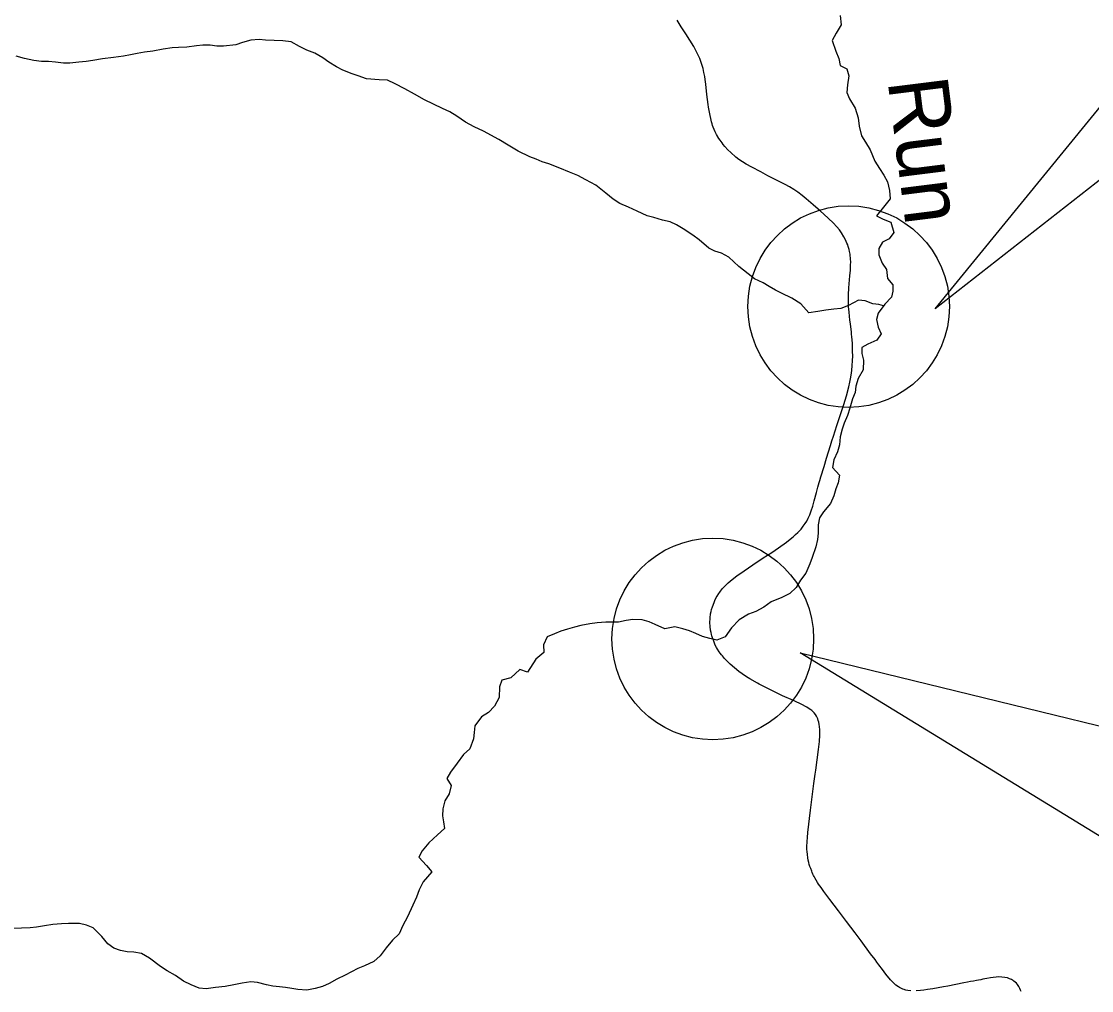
# Model space of a CAD drawing. Extents: x -12.1 to 34, y 0 to 22.
# Drawn here: x 3.691 to 5.273, y 14.772 to 16.204 of the extents above; entities that cross this region are included whole.
import ezdxf

# ---------------------------------------------------------------- set-up
doc = ezdxf.new("R2010")
doc.units = 0
for name, color, linetype in [('BR_P_Gen_Text', 7, 'Continuous'), ('Default', 7, 'Continuous'), ('GM_X_Minor_River', 7, 'Continuous'), ('GM_X_Minor_River_Text', 7, 'Continuous'), ('GM_X_State_Route', 7, 'Continuous')]:
    doc.layers.add(name, color=color, linetype=linetype)

msp = doc.modelspace()

# ---------------------------------------------------------------- linework, layer by layer
at = {"layer": 'BR_P_Gen_Text'}
for points in [[(5.7213, 16.6121), (5.7213, 16.3119), (5.0417, 15.7796)], [(5.6572, 15.0721), (5.6572, 14.7719), (4.8418, 15.271)]]:
    msp.add_lwpolyline(points, close=True, dxfattribs=at)
at = {"layer": 'Default'}
for centre in [(4.9136, 15.7828), (4.7128, 15.2916)]:
    msp.add_circle(centre, 0.149, dxfattribs=at)
at = {"layer": 'GM_X_Minor_River'}
for points in [[(4.9012, 16.2129), (4.9024, 16.1994), (4.8951, 16.1869), (4.8895, 16.1762), (4.8946, 16.1606), (4.899, 16.1496), (4.9012, 16.1394), (4.9108, 16.1345), (4.9138, 16.1238), (4.9118, 16.1107), (4.9108, 16.0993), (4.9148, 16.0898), (4.9234, 16.0763), (4.9278, 16.0618), (4.9293, 16.0494), (4.9327, 16.0352), (4.9384, 16.0257), (4.9453, 16.0147), (4.9525, 15.9977), (4.9594, 15.9868), (4.9658, 15.9773), (4.9709, 15.967), (4.9739, 15.9546), (4.975, 15.9422), (4.9652, 15.93), (4.955, 15.9171), (4.9647, 15.9122), (4.9761, 15.9074), (4.9805, 15.8925), (4.9735, 15.8832), (4.9639, 15.8781), (4.9583, 15.8685), (4.9581, 15.8592), (4.9631, 15.8468), (4.9696, 15.8377), (4.9712, 15.8245), (4.9787, 15.815), (4.9788, 15.8058), (4.9771, 15.7969), (4.9672, 15.7865), (4.9574, 15.7729), (4.9547, 15.7636), (4.9573, 15.7526), (4.9616, 15.7424), (4.9553, 15.7331), (4.9422, 15.7273), (4.9331, 15.7226), (4.9331, 15.7137), (4.9354, 15.7037), (4.9351, 15.6895), (4.9278, 15.6767), (4.9244, 15.6653), (4.9234, 15.6557), (4.9192, 15.6464), (4.9154, 15.6325), (4.912, 15.6218)], [(4.9653, 15.7838), (4.9584, 15.7857), (4.9495, 15.7867), (4.9381, 15.7912), (4.9282, 15.7925), (4.9133, 15.7845), (4.902, 15.7802), (4.8917, 15.779), (4.8801, 15.7775), (4.868, 15.7756), (4.8549, 15.7737), (4.8431, 15.7871), (4.8295, 15.7954), (4.8142, 15.8028), (4.8053, 15.8073), (4.7963, 15.8125), (4.7874, 15.8181), (4.7746, 15.8237), (4.7653, 15.8314), (4.7514, 15.8423), (4.7367, 15.856), (4.7256, 15.8616), (4.716, 15.865), (4.7071, 15.8692), (4.6925, 15.8815), (4.6835, 15.8882), (4.6689, 15.898), (4.6593, 15.9039), (4.6496, 15.9081), (4.6386, 15.9108), (4.6255, 15.9143), (4.6159, 15.917), (4.6009, 15.924), (4.5884, 15.9299), (4.5756, 15.9354), (4.5656, 15.9417), (4.5549, 15.9505), (4.5399, 15.9621), (4.5252, 15.9701), (4.5135, 15.9764), (4.501, 15.9816), (4.4868, 15.9875), (4.4704, 15.9938), (4.4604, 15.9969), (4.4515, 16.0007), (4.4423, 16.0041), (4.4252, 16.0125), (4.4102, 16.0212), (4.3966, 16.0296), (4.3738, 16.0422), (4.3599, 16.0485), (4.3471, 16.0554), (4.3346, 16.0642), (4.3242, 16.0705), (4.3132, 16.0757), (4.3, 16.082), (4.2864, 16.0882), (4.2718, 16.0966), (4.2576, 16.1047), (4.2433, 16.112), (4.2319, 16.1176), (4.2195, 16.1178), (4.201, 16.1197), (4.1885, 16.1239), (4.1796, 16.127), (4.1661, 16.1325), (4.1565, 16.1371), (4.1454, 16.1441), (4.1365, 16.1504), (4.1244, 16.1574), (4.1126, 16.1619), (4.1019, 16.1671), (4.0895, 16.1741), (4.077, 16.1757), (4.0646, 16.1763), (4.0515, 16.1765), (4.0422, 16.1775), (4.0298, 16.1767), (4.0174, 16.173), (4.0075, 16.1697), (3.9895, 16.1678), (3.9795, 16.168), (3.9699, 16.169), (3.9589, 16.1692), (3.9494, 16.1681), (3.9352, 16.1662), (3.9231, 16.166), (3.9136, 16.1652), (3.9001, 16.1633), (3.8849, 16.1603), (3.8728, 16.1588), (3.8618, 16.1569), (3.8519, 16.155), (3.8416, 16.1528), (3.8271, 16.1509), (3.8105, 16.1489), (3.7963, 16.1467), (3.7864, 16.1451), (3.7757, 16.144), (3.7626, 16.1428), (3.753, 16.1427)], [(3.753, 16.1427), (3.7413, 16.1443), (3.731, 16.1449), (3.7204, 16.1452), (3.709, 16.1465), (3.6955, 16.1496), (3.6831, 16.153)], [(4.912, 15.6218), (4.9068, 15.6107), (4.904, 15.6015), (4.9013, 15.5901), (4.9003, 15.5783), (4.8972, 15.568), (4.8917, 15.5562), (4.8896, 15.5448), (4.9, 15.5336), (4.898, 15.5222), (4.8945, 15.5133), (4.8918, 15.5029), (4.8866, 15.4919), (4.8764, 15.4797), (4.8705, 15.4704), (4.8684, 15.4601), (4.8685, 15.448), (4.8676, 15.4387), (4.8652, 15.4277), (4.8596, 15.412), (4.8562, 15.4027), (4.8503, 15.3888), (4.8426, 15.3785), (4.8359, 15.3677), (4.8268, 15.3588), (4.8148, 15.353), (4.7992, 15.3464), (4.7883, 15.3388), (4.7766, 15.332), (4.7657, 15.328), (4.7519, 15.32), (4.7403, 15.3078), (4.7309, 15.2949), (4.7188, 15.2898), (4.7082, 15.2922), (4.6975, 15.2953), (4.6875, 15.2995), (4.6783, 15.3037), (4.6687, 15.3068), (4.6569, 15.3095), (4.6421, 15.3065), (4.6274, 15.3131), (4.6185, 15.3169), (4.6086, 15.32), (4.5947, 15.3206), (4.5848, 15.3191), (4.5735, 15.3165), (4.5547, 15.3163), (4.5419, 15.3155), (4.5309, 15.3139), (4.5178, 15.3113), (4.5086, 15.3091), (4.498, 15.3062), (4.4881, 15.3029), (4.4786, 15.2992), (4.468, 15.2945), (4.4627, 15.2831), (4.4629, 15.2714), (4.4512, 15.2616), (4.439, 15.2423), (4.4276, 15.2465), (4.4142, 15.2339), (4.4011, 15.2306), (4.3973, 15.221), (4.3968, 15.205), (4.3901, 15.1921), (4.3813, 15.1831), (4.3711, 15.1767), (4.361, 15.1634), (4.36, 15.1535), (4.359, 15.1442), (4.3538, 15.1292), (4.3443, 15.121), (4.3349, 15.1081), (4.325, 15.0948), (4.3198, 15.0855), (4.3263, 15.0749), (4.3232, 15.0625), (4.3166, 15.0525), (4.3135, 15.0404), (4.3132, 15.0304), (4.3147, 15.0212), (4.3162, 15.0112), (4.306, 15.0023), (4.293, 14.9904), (4.2832, 14.9782), (4.2783, 14.9689), (4.2898, 14.9566), (4.2973, 14.9475), (4.2847, 14.9328), (4.2788, 14.9206), (4.2746, 14.9099), (4.2694, 14.8982), (4.2614, 14.881), (4.2548, 14.8682), (4.2492, 14.8557), (4.2393, 14.8463), (4.2299, 14.8349), (4.2211, 14.8234), (4.2116, 14.8148), (4.1978, 14.8086)], [(4.1978, 14.8086), (4.1883, 14.8046), (4.1692, 14.7948), (4.1569, 14.7887), (4.1459, 14.7825), (4.136, 14.7778), (4.1251, 14.7748), (4.1127, 14.7726), (4.0995, 14.7735), (4.0903, 14.7749), (4.0814, 14.7762), (4.0725, 14.7775), (4.0626, 14.7785), (4.0533, 14.7805), (4.0398, 14.784), (4.0299, 14.7846), (4.0171, 14.7827), (4.0047, 14.7804), (3.992, 14.7778), (3.9778, 14.7762), (3.964, 14.7747), (3.9537, 14.7753), (3.9416, 14.7805), (3.9302, 14.7857), (3.9184, 14.7941), (3.9063, 14.8011), (3.8963, 14.8074), (3.8802, 14.82), (3.8681, 14.8267), (3.8571, 14.8287), (3.8471, 14.8293), (3.8375, 14.8313), (3.8272, 14.8348), (3.8183, 14.8411), (3.8097, 14.8517), (3.7968, 14.8647), (3.7871, 14.8685), (3.7765, 14.8709), (3.7602, 14.8711), (3.7499, 14.8703), (3.7371, 14.8694), (3.7247, 14.8675), (3.713, 14.8656), (3.7038, 14.8648), (3.691, 14.8643), (3.6761, 14.8635)]]:
    msp.add_lwpolyline(points, dxfattribs=at)
at = {"layer": 'GM_X_State_Route'}
for points in [[(4.7093, 15.3269), (4.7096, 15.3289), (4.7102, 15.3322), (4.7109, 15.3349), (4.7123, 15.3393), (4.7147, 15.3456), (4.7158, 15.3483), (4.718, 15.3528), (4.7192, 15.3549), (4.7217, 15.3587), (4.723, 15.3606), (4.7268, 15.3655), (4.7301, 15.3691), (4.7316, 15.3707), (4.7354, 15.3744), (4.7413, 15.3796), (4.7483, 15.385), (4.759, 15.3923), (4.772, 15.401), (4.7874, 15.4113), (4.8, 15.4196), (4.8101, 15.4265), (4.8219, 15.4349), (4.8274, 15.4392), (4.8314, 15.4425), (4.8353, 15.4459), (4.8386, 15.449), (4.8407, 15.4511), (4.8434, 15.4541), (4.8466, 15.4581), (4.8494, 15.462), (4.8516, 15.4657), (4.8539, 15.47), (4.8561, 15.4751), (4.8582, 15.4808), (4.8605, 15.488), (4.8627, 15.4957), (4.866, 15.508), (4.8682, 15.5159), (4.8701, 15.5229), (4.871, 15.526), (4.8725, 15.5312), (4.8772, 15.5464), (4.881, 15.5588), (4.8838, 15.568), (4.8867, 15.5775), (4.8889, 15.5845), (4.8911, 15.5914), (4.8963, 15.6073), (4.9026, 15.6264), (4.9063, 15.6381), (4.9102, 15.651), (4.9139, 15.6643), (4.9153, 15.671), (4.9164, 15.676), (4.9168, 15.6785), (4.9178, 15.685), (4.9182, 15.6886), (4.919, 15.6958), (4.9194, 15.7027), (4.9196, 15.7103), (4.9195, 15.7166), (4.9195, 15.7221), (4.9192, 15.7281), (4.9188, 15.7339), (4.9184, 15.7383), (4.918, 15.7422), (4.9176, 15.7457), (4.9172, 15.7491), (4.9162, 15.7575), (4.9155, 15.7628), (4.9143, 15.7745), (4.9136, 15.7828), (4.9134, 15.7905), (4.9132, 15.8003), (4.9138, 15.8104), (4.9154, 15.8282), (4.9163, 15.8368), (4.9166, 15.8434), (4.9167, 15.8495), (4.9166, 15.8524), (4.9157, 15.8605), (4.9149, 15.8644), (4.9142, 15.8673), (4.9129, 15.8717), (4.9122, 15.874), (4.9111, 15.8767), (4.9089, 15.8817), (4.9066, 15.8861), (4.903, 15.8918), (4.8999, 15.8961), (4.8962, 15.9006), (4.8907, 15.9064), (4.884, 15.9128), (4.8767, 15.9195), (4.8718, 15.9238), (4.8612, 15.9332), (4.8506, 15.9422), (4.8449, 15.947), (4.8385, 15.9519), (4.8326, 15.9559), (4.8262, 15.9597), (4.82, 15.9631), (4.8082, 15.9692), (4.7944, 15.9763), (4.7837, 15.982), (4.7704, 15.9888), (4.7623, 15.9932), (4.7567, 15.9967), (4.7515, 16.0003), (4.7469, 16.0039), (4.7397, 16.0104), (4.7352, 16.0146), (4.7308, 16.0195), (4.7283, 16.0225), (4.7265, 16.025), (4.7237, 16.0288), (4.7219, 16.0315), (4.7184, 16.0374), (4.7164, 16.0413), (4.715, 16.0444), (4.7134, 16.048), (4.7125, 16.0507), (4.7118, 16.0528), (4.7109, 16.0559), (4.7104, 16.0584), (4.7084, 16.0675), (4.7065, 16.0778), (4.706, 16.0815), (4.7042, 16.0964), (4.7026, 16.1116), (4.7017, 16.1186), (4.701, 16.1228), (4.6997, 16.129), (4.6984, 16.1346), (4.6961, 16.1423), (4.6934, 16.1496), (4.6899, 16.1573), (4.6846, 16.1673), (4.6787, 16.1768), (4.6728, 16.1859), (4.6662, 16.1961), (4.6599, 16.2062)], [(5.0054, 14.7715), (5.001, 14.7721), (4.998, 14.7727), (4.9967, 14.773), (4.9956, 14.7734), (4.9936, 14.7742), (4.9917, 14.775), (4.9888, 14.7766), (4.9874, 14.7774), (4.9836, 14.78), (4.9808, 14.7825), (4.9793, 14.7839), (4.9757, 14.7877), (4.9688, 14.7962), (4.9636, 14.803), (4.9584, 14.8099), (4.9554, 14.8139), (4.9526, 14.8176), (4.9459, 14.8264), (4.9319, 14.8456), (4.9231, 14.857), (4.9103, 14.8742), (4.8984, 14.8898), (4.8859, 14.9063), (4.8771, 14.9181), (4.8728, 14.9242), (4.8691, 14.9294), (4.8676, 14.9318), (4.8636, 14.9387), (4.8626, 14.9404), (4.8617, 14.9422), (4.8609, 14.9438), (4.8599, 14.9462), (4.859, 14.9482), (4.8575, 14.9521), (4.8563, 14.9554), (4.8555, 14.9581), (4.8547, 14.961), (4.8539, 14.9645), (4.8533, 14.9679), (4.8526, 14.973), (4.8521, 14.9775), (4.852, 14.9804), (4.8519, 14.9842), (4.8524, 14.9924), (4.8527, 14.9981), (4.8533, 15.0057), (4.8571, 15.0385), (4.8622, 15.078), (4.8642, 15.0919), (4.865, 15.0976), (4.8669, 15.113), (4.869, 15.1284), (4.8704, 15.1398), (4.8709, 15.1493), (4.871, 15.1519), (4.8708, 15.1571), (4.8704, 15.1621), (4.87, 15.165), (4.8694, 15.1685), (4.8687, 15.1711), (4.8679, 15.1733), (4.867, 15.1754), (4.866, 15.1776), (4.8646, 15.1798), (4.8625, 15.1825), (4.8604, 15.1847), (4.859, 15.186), (4.8577, 15.187), (4.8555, 15.1885), (4.852, 15.1907), (4.8499, 15.1919), (4.8456, 15.194), (4.8319, 15.2004), (4.8159, 15.2076), (4.7992, 15.2158), (4.7864, 15.2223), (4.7814, 15.2248), (4.7791, 15.2261), (4.7677, 15.2326), (4.7626, 15.2358), (4.7564, 15.24), (4.7511, 15.2437), (4.7447, 15.2488), (4.7385, 15.2542), (4.7339, 15.2587), (4.7303, 15.2626), (4.727, 15.2665), (4.7256, 15.2682), (4.7237, 15.2708), (4.7223, 15.2728), (4.7197, 15.2767), (4.7182, 15.2792), (4.7165, 15.2824), (4.7146, 15.2867), (4.7136, 15.2896), (4.7128, 15.2916), (4.7114, 15.296), (4.7109, 15.298), (4.7102, 15.301), (4.7095, 15.3045), (4.7089, 15.3099), (4.7086, 15.3161), (4.7087, 15.3217), (4.709, 15.3247), (4.7093, 15.3269)], [(5.1685, 14.7704), (5.1679, 14.7724), (5.1667, 14.7752), (5.1651, 14.7781), (5.1643, 14.7793), (5.1631, 14.781), (5.1616, 14.7828), (5.1598, 14.7844), (5.158, 14.7859), (5.157, 14.7866), (5.1556, 14.7874), (5.1543, 14.7881), (5.1515, 14.7894), (5.1483, 14.7905), (5.1443, 14.7914), (5.1403, 14.7919), (5.1358, 14.792), (5.1319, 14.7918), (5.1273, 14.7912), (5.1234, 14.7905), (5.1177, 14.7896), (5.1122, 14.7886), (5.1091, 14.7879), (5.1056, 14.7873), (5.1024, 14.7867), (5.0983, 14.786), (5.0936, 14.7851), (5.0895, 14.7842), (5.084, 14.7832), (5.0721, 14.7808), (5.06, 14.7786), (5.0536, 14.7774), (5.0459, 14.776), (5.0382, 14.7747), (5.0301, 14.7733), (5.0247, 14.7725), (5.0196, 14.7719), (5.0134, 14.7714)]]:
    msp.add_lwpolyline(points, dxfattribs=at)

# ---------------------------------------------------------------- texts
at = {"layer": 'GM_X_Minor_River_Text'}
msp.add_text('Run', height=0.08877, rotation=277.0886, dxfattribs=at).set_placement((4.9711, 16.1168))

doc.saveas('drawing.dxf')
